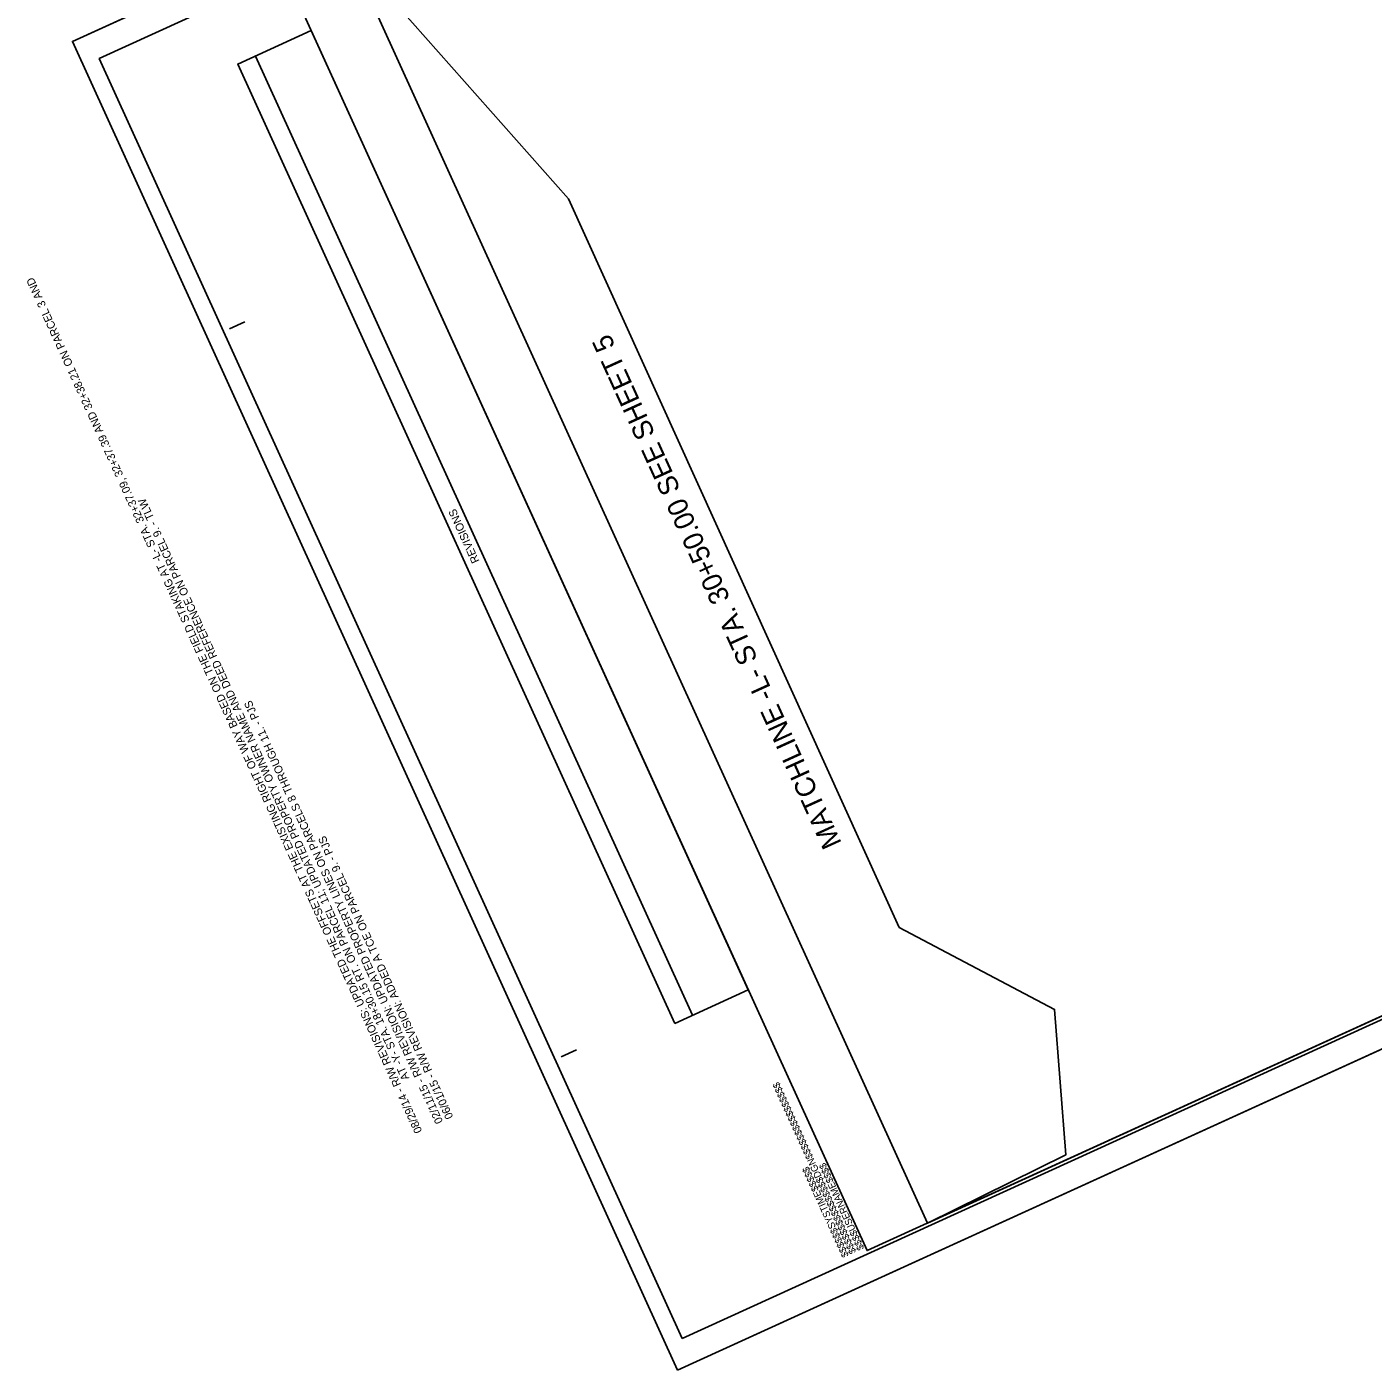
# Model space of a CAD drawing. Extents: x 2249019 to 2251039, y 663030 to 664799.
# Drawn here: x 2249019 to 2250029, y 663030 to 664038 of the extents above; entities that cross this region are included whole.
import ezdxf

# ---------------------------------------------------------------- set-up
doc = ezdxf.new("R2010")
doc.units = 0
for name, color, linetype in [('Matchline', 7, 'Continuous'), ('Matchline Text', 7, 'Continuous'), ('Prop Dimension Text', 7, 'Continuous'), ('Sheet Block Revision CELL', 7, 'Continuous'), ('Sheet Clip Boundary CELL', 7, 'Continuous'), ('Sheet Cutting Line CELL', 7, 'Continuous'), ('Sheet Layout Plan Border', 7, 'Continuous'), ('Sheet Plan CELL', 7, 'Continuous'), ('Sheet Plan Layout CELL', 7, 'Continuous'), ('Sheet Plot Border Inside CELL', 7, 'Continuous'), ('Sheet Plot Border Outside CELL', 7, 'Continuous')]:
    doc.layers.add(name, color=color, linetype=linetype)

msp = doc.modelspace()

# ---------------------------------------------------------------- linework, layer by layer
at = {"layer": 'Matchline'}
msp.add_line((2249673.4, 663362.4), (2249425.3, 663908.7), dxfattribs=at)
at = {"layer": 'Sheet Block Revision CELL'}
msp.add_line((2249518.3, 663296.5), (2249190.4, 664015.9), dxfattribs=at)
msp.add_lwpolyline([(2249505.1, 663290.4), (2249177.2, 664009.9), (2249232.3, 664035), (2249560.1, 663315.5)], close=True, dxfattribs=at)
at = {"layer": 'Sheet Clip Boundary CELL'}
msp.add_lwpolyline([(2249425.3, 663908.7), (2249673.4, 663362.4), (2249790, 663300.9), (2249798.4, 663191.7), (2249694.8, 663140.6), (2250968.8, 663721.1), (2250621.1, 664484.2), (2250448.8, 664405.7), (2250361.1, 664598.1), (2249259.4, 664096.1)], close=True, dxfattribs=at)
at = {"layer": 'Sheet Cutting Line CELL'}
for p, q in [((2250585, 664724.9), (2249053.1, 664026.8)), ((2249053.1, 664026.8), (2249507.1, 663030.3)), ((2249507.1, 663030.3), (2251039.1, 663728.4))]:
    msp.add_line(p, q, dxfattribs=at)
at = {"layer": 'Sheet Layout Plan Border'}
msp.add_lwpolyline([(2249694.8, 663140.6), (2250968.8, 663721.1), (2250621.1, 664484.2), (2250448.8, 664405.7), (2250361.1, 664598.1), (2249259.4, 664096.1)], close=True, dxfattribs=at)
at = {"layer": 'Sheet Plan CELL'}
for p, q in [((2249171, 663811.3), (2249182.4, 663816.5)), ((2249419.8, 663265.3), (2249431.2, 663270.5)), ((2249649.3, 663119.9), (2249649.3, 663119.9))]:
    msp.add_line(p, q, dxfattribs=at)
for points in [[(2250578.9, 664697.4), (2249213.9, 664075.3), (2249649.3, 663119.9), (2251014.2, 663741.9)], [(2249649.3, 663119.9), (2249213.9, 664075.3), (2250396.8, 664614.4), (2250459, 664477.9), (2250641.1, 664560.8), (2251014.2, 663741.9)]]:
    msp.add_lwpolyline(points, close=True, dxfattribs=at)
at = {"layer": 'Sheet Plan Layout CELL'}
msp.add_lwpolyline([(2249213.9, 664075.3), (2249649.3, 663119.9), (2251014.2, 663741.9), (2250666.5, 664504.9), (2250448.8, 664405.7), (2250361.1, 664598.1)], close=True, dxfattribs=at)
at = {"layer": 'Sheet Plot Border Inside CELL'}
msp.add_lwpolyline([(2249510.6, 663053.9), (2251026.6, 663744.8), (2250589.2, 664704.8), (2249073.2, 664014)], close=True, dxfattribs=at)
at = {"layer": 'Sheet Plot Border Outside CELL'}
msp.add_lwpolyline([(2249507.1, 663030.3), (2251039.1, 663728.4), (2250585, 664724.9), (2249053.1, 664026.8)], close=True, dxfattribs=at)

# ---------------------------------------------------------------- texts
at = {"layer": 'Matchline Text'}
msp.add_text('MATCHLINE -L- STA. 30+50.00 SEE SHEET 5', height=15, rotation=114.4979, dxfattribs=at).set_placement((2249630.5, 663425.5))
at = {"layer": 'Prop Dimension Text'}
for s, p in [('08/29/14 - R/W REVISIONS: UPDATED THE OFFSETS AT THE EXISTING RIGHT OF WAY BASED ON THE FIELD STAKING AT -L- STA. 32+37.09, 32+37.39 AND 32+38.21 ON PARCEL 3 AND', (2249315.7, 663209.6)), ('                  AT -Y- STA. 18+30.15 RT. ON PARCEL 11; UPDATED PROPERTY OWNER NAME AND DEED REFERENCE ON PARCEL 9. - TLW ', (2249322.7, 663212.8)), ('02/11/15 - R/W REVISION: UPDATED PROPERTY LINES ON PARCELS 8 THROUGH 11. - PJS', (2249331.3, 663216.7)), ('06/01/15 - R/W REVISION: ADDED A TCE ON PARCEL 9. - PJS', (2249339, 663220.2))]:
    msp.add_text(s, height=6, rotation=114.4979, dxfattribs=at).set_placement(p)
at = {"layer": 'Sheet Block Revision CELL'}
msp.add_text('REVISIONS', height=6, rotation=114.4979, dxfattribs=at).set_placement((2249358.6, 663637.1))
at = {"layer": 'Sheet Plan CELL'}
for s, p in [('$$$$$$$$$$$$$$$$DGN$$$$$$$$$$$$$$$$', (2249641.3, 663118.9)), ('$$$$$$SYSTIME$$$$$', (2249635.8, 663116.3)), ('$$$$USERNAME$$$$', (2249647.3, 663121.6))]:
    msp.add_text(s, height=5.25, rotation=114.4979, dxfattribs=at).set_placement(p)

doc.saveas('drawing.dxf')
